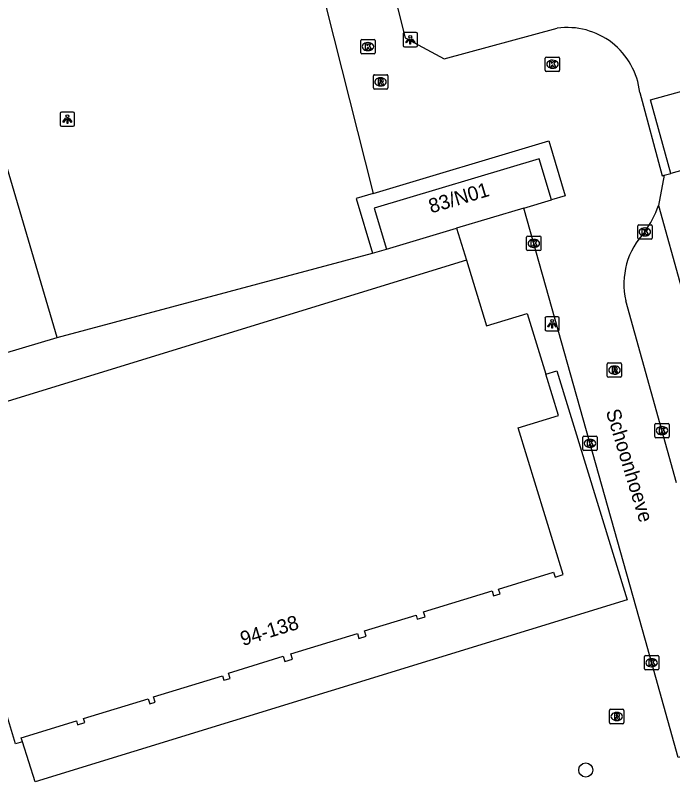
# Model space of a CAD drawing. Extents: x 161801 to 162379, y 382315 to 382832.
# Drawn here: x 161896.7 to 161942.5, y 382359.5 to 382412.7 of the extents above; entities that cross this region are included whole.
import ezdxf

# ---------------------------------------------------------------- set-up
doc = ezdxf.new("R2010")
doc.units = 0
for name, color, linetype in [('IMGEO_Boom', 7, 'Continuous'), ('IMGEO_Kolk', 7, 'Continuous'), ('IMGEO_Lichtpunt', 7, 'Continuous'), ('IMGEO_Openbare_ruimte_label', 7, 'Continuous'), ('IMGEO_Pand', 7, 'Continuous'), ('IMGEO_Pand_nummerreeks', 7, 'Continuous'), ('IMGEO_Rijbaan_lokaal_open', 7, 'Continuous'), ('IMGEO_Rioolput', 7, 'Continuous'), ('IMGEO_Voetpad_open', 7, 'Continuous')]:
    doc.layers.add(name, color=color, linetype=linetype)

msp = doc.modelspace()

# ---------------------------------------------------------------- linework, layer by layer
at = {"layer": 'IMGEO_Boom'}
msp.add_circle((161936.434, 382360.086), 0.489, dxfattribs=at)
at = {"layer": 'IMGEO_Kolk'}
for p, q in [((161920.83, 382411.017), (161921.682, 382411.017)), ((161920.755, 382410.091), (161920.755, 382410.943)), ((161921.243, 382410.797), (161921.268, 382410.797)), ((161921.756, 382410.943), (161921.756, 382410.091)), ((161921.682, 382410.017), (161920.83, 382410.017)), ((161921.266, 382410.237), (161921.241, 382410.237)), ((161933.616, 382408.865), (161933.616, 382409.717)), ((161933.691, 382409.791), (161934.543, 382409.791)), ((161934.104, 382409.571), (161934.129, 382409.571)), ((161934.617, 382409.717), (161934.617, 382408.865)), ((161934.127, 382409.011), (161934.102, 382409.011)), ((161934.543, 382408.791), (161933.691, 382408.791)), ((161940.056, 382397.172), (161940.056, 382398.024)), ((161940.131, 382398.098), (161940.983, 382398.098)), ((161940.544, 382397.878), (161940.569, 382397.878)), ((161941.057, 382398.024), (161941.057, 382397.172)), ((161932.316, 382396.372), (161932.316, 382397.224)), ((161932.391, 382397.298), (161933.243, 382397.298)), ((161933.317, 382397.224), (161933.317, 382396.372)), ((161940.567, 382397.318), (161940.542, 382397.318)), ((161932.804, 382397.078), (161932.829, 382397.078)), ((161940.983, 382397.098), (161940.131, 382397.098)), ((161933.243, 382396.298), (161932.391, 382396.298)), ((161932.827, 382396.518), (161932.802, 382396.518)), ((161941.247, 382383.326), (161941.247, 382384.178)), ((161941.322, 382384.252), (161942.174, 382384.252)), ((161941.735, 382384.032), (161941.76, 382384.032)), ((161942.248, 382384.178), (161942.248, 382383.326)), ((161936.306, 382383.359), (161937.158, 382383.359)), ((161941.758, 382383.472), (161941.733, 382383.472)), ((161936.231, 382382.433), (161936.231, 382383.285)), ((161936.719, 382383.139), (161936.744, 382383.139)), ((161937.232, 382383.285), (161937.232, 382382.433)), ((161942.174, 382383.252), (161941.322, 382383.252)), ((161937.158, 382382.359), (161936.306, 382382.359)), ((161936.742, 382382.579), (161936.717, 382382.579)), ((161940.526, 382367.136), (161940.526, 382367.988)), ((161940.601, 382368.062), (161941.453, 382368.062)), ((161941.527, 382367.988), (161941.527, 382367.136)), ((161941.014, 382367.842), (161941.039, 382367.842)), ((161941.453, 382367.062), (161940.601, 382367.062)), ((161941.037, 382367.282), (161941.012, 382367.282))]:
    msp.add_line(p, q, dxfattribs=at)
for points in [[(161920.83, 382411.017), (161921.682, 382411.017)], [(161920.755, 382410.091), (161920.755, 382410.943)], [(161921.076, 382410.717), (161921.199, 382410.717), (161921.199, 382410.566), (161921.329, 382410.717), (161921.493, 382410.717), (161921.347, 382410.566), (161921.5, 382410.317), (161921.348, 382410.317), (161921.263, 382410.481), (161921.199, 382410.414), (161921.199, 382410.317), (161921.076, 382410.317), (161921.076, 382410.717)], [(161921.756, 382410.943), (161921.756, 382410.091)], [(161921.682, 382410.017), (161920.83, 382410.017)], [(161933.616, 382408.865), (161933.616, 382409.717)], [(161933.691, 382409.791), (161934.543, 382409.791)], [(161933.937, 382409.491), (161934.06, 382409.491), (161934.06, 382409.34), (161934.19, 382409.491), (161934.354, 382409.491), (161934.208, 382409.34), (161934.361, 382409.091), (161934.209, 382409.091), (161934.124, 382409.255), (161934.06, 382409.188), (161934.06, 382409.091), (161933.937, 382409.091), (161933.937, 382409.491)], [(161934.617, 382409.717), (161934.617, 382408.865)], [(161934.543, 382408.791), (161933.691, 382408.791)], [(161940.056, 382397.172), (161940.056, 382398.024)], [(161940.131, 382398.098), (161940.983, 382398.098)], [(161940.377, 382397.798), (161940.5, 382397.798), (161940.5, 382397.647), (161940.63, 382397.798), (161940.794, 382397.798), (161940.648, 382397.647), (161940.801, 382397.398), (161940.649, 382397.398), (161940.564, 382397.562), (161940.5, 382397.495), (161940.5, 382397.398), (161940.377, 382397.398), (161940.377, 382397.798)], [(161941.057, 382398.024), (161941.057, 382397.172)], [(161932.316, 382396.372), (161932.316, 382397.224)], [(161932.391, 382397.298), (161933.243, 382397.298)], [(161933.317, 382397.224), (161933.317, 382396.372)], [(161932.637, 382396.998), (161932.76, 382396.998), (161932.76, 382396.847), (161932.89, 382396.998), (161933.054, 382396.998), (161932.908, 382396.847), (161933.061, 382396.598), (161932.909, 382396.598), (161932.824, 382396.762), (161932.76, 382396.695), (161932.76, 382396.598), (161932.637, 382396.598), (161932.637, 382396.998)], [(161940.983, 382397.098), (161940.131, 382397.098)], [(161933.243, 382396.298), (161932.391, 382396.298)], [(161941.247, 382383.326), (161941.247, 382384.178)], [(161941.322, 382384.252), (161942.174, 382384.252)], [(161941.568, 382383.952), (161941.691, 382383.952), (161941.691, 382383.801), (161941.821, 382383.952), (161941.985, 382383.952), (161941.839, 382383.801), (161941.992, 382383.552), (161941.84, 382383.552), (161941.755, 382383.716), (161941.691, 382383.649), (161941.691, 382383.552), (161941.568, 382383.552), (161941.568, 382383.952)], [(161942.248, 382384.178), (161942.248, 382383.326)], [(161936.306, 382383.359), (161937.158, 382383.359)], [(161936.231, 382382.433), (161936.231, 382383.285)], [(161936.552, 382383.059), (161936.675, 382383.059), (161936.675, 382382.908), (161936.805, 382383.059), (161936.969, 382383.059), (161936.823, 382382.908), (161936.976, 382382.659), (161936.824, 382382.659), (161936.739, 382382.823), (161936.675, 382382.756), (161936.675, 382382.659), (161936.552, 382382.659), (161936.552, 382383.059)], [(161937.232, 382383.285), (161937.232, 382382.433)], [(161942.174, 382383.252), (161941.322, 382383.252)], [(161937.158, 382382.359), (161936.306, 382382.359)], [(161940.526, 382367.136), (161940.526, 382367.988)], [(161940.601, 382368.062), (161941.453, 382368.062)], [(161941.527, 382367.988), (161941.527, 382367.136)], [(161940.847, 382367.762), (161940.97, 382367.762), (161940.97, 382367.611), (161941.1, 382367.762), (161941.264, 382367.762), (161941.118, 382367.611), (161941.271, 382367.362), (161941.119, 382367.362), (161941.034, 382367.526), (161940.97, 382367.459), (161940.97, 382367.362), (161940.847, 382367.362), (161940.847, 382367.762)], [(161941.453, 382367.062), (161940.601, 382367.062)]]:
    msp.add_lwpolyline(points, dxfattribs=at)
for centre, start, end in [((161920.832, 382410.941), 91.552, 178.448), ((161920.832, 382410.941), 91.552, 178.448), ((161921.68, 382410.941), 1.552, 88.448), ((161921.68, 382410.941), 1.552, 88.448), ((161920.832, 382410.093), 181.552, 268.448), ((161920.832, 382410.093), 181.552, 268.448), ((161921.68, 382410.093), 271.552, 358.448), ((161921.68, 382410.093), 271.552, 358.448), ((161933.693, 382409.715), 91.552, 178.448), ((161933.693, 382409.715), 91.552, 178.448), ((161934.541, 382409.715), 1.552, 88.448), ((161934.541, 382409.715), 1.552, 88.448), ((161933.693, 382408.867), 181.552, 268.448), ((161933.693, 382408.867), 181.552, 268.448), ((161934.541, 382408.867), 271.552, 358.448), ((161934.541, 382408.867), 271.552, 358.448), ((161940.133, 382398.022), 91.552, 178.448), ((161940.133, 382398.022), 91.552, 178.448), ((161940.981, 382398.022), 1.552, 88.448), ((161940.981, 382398.022), 1.552, 88.448), ((161932.393, 382397.222), 91.552, 178.448), ((161932.393, 382397.222), 91.552, 178.448), ((161933.241, 382397.222), 1.552, 88.448), ((161933.241, 382397.222), 1.552, 88.448), ((161940.133, 382397.174), 181.552, 268.448), ((161940.133, 382397.174), 181.552, 268.448), ((161940.981, 382397.174), 271.552, 358.448), ((161940.981, 382397.174), 271.552, 358.448), ((161932.393, 382396.374), 181.552, 268.448), ((161932.393, 382396.374), 181.552, 268.448), ((161933.241, 382396.374), 271.552, 358.448), ((161933.241, 382396.374), 271.552, 358.448), ((161941.324, 382384.176), 91.552, 178.448), ((161941.324, 382384.176), 91.552, 178.448), ((161942.172, 382384.176), 1.552, 88.448), ((161942.172, 382384.176), 1.552, 88.448), ((161936.308, 382383.283), 91.552, 178.448), ((161936.308, 382383.283), 91.552, 178.448), ((161937.156, 382383.283), 1.552, 88.448), ((161937.156, 382383.283), 1.552, 88.448), ((161941.324, 382383.328), 181.552, 268.448), ((161941.324, 382383.328), 181.552, 268.448), ((161942.172, 382383.328), 271.552, 358.448), ((161942.172, 382383.328), 271.552, 358.448), ((161936.308, 382382.435), 181.552, 268.448), ((161936.308, 382382.435), 181.552, 268.448), ((161937.156, 382382.435), 271.552, 358.448), ((161937.156, 382382.435), 271.552, 358.448), ((161940.603, 382367.986), 91.552, 178.448), ((161940.603, 382367.986), 91.552, 178.448), ((161941.451, 382367.986), 1.552, 88.448), ((161941.451, 382367.986), 1.552, 88.448), ((161940.603, 382367.138), 181.552, 268.448), ((161940.603, 382367.138), 181.552, 268.448), ((161941.451, 382367.138), 271.552, 358.448), ((161941.451, 382367.138), 271.552, 358.448)]:
    msp.add_arc(centre, 0.0765, start, end, dxfattribs=at)
for centre, major_axis, ratio, start_param, end_param in [((161921.242, 382410.517), (-0.387, 0.002), 0.722429, 4.712389, 7.853982), ((161921.267, 382410.517), (-0.39, 0.002), 0.717154, 1.570796, 4.712389), ((161934.103, 382409.291), (-0.387, 0.002), 0.722429, 4.712389, 7.853982), ((161934.128, 382409.291), (-0.39, 0.002), 0.717154, 1.570796, 4.712389), ((161940.543, 382397.598), (-0.387, 0.002), 0.722429, 4.712389, 7.853982), ((161940.568, 382397.598), (-0.39, 0.002), 0.717154, 1.570796, 4.712389), ((161932.803, 382396.798), (-0.387, 0.002), 0.722429, 4.712389, 7.853982), ((161932.828, 382396.798), (-0.39, 0.002), 0.717154, 1.570796, 4.712389), ((161941.734, 382383.752), (-0.387, 0.002), 0.722429, 4.712389, 7.853982), ((161941.759, 382383.752), (-0.39, 0.002), 0.717154, 1.570796, 4.712389), ((161936.718, 382382.859), (-0.387, 0.002), 0.722429, 4.712389, 7.853982), ((161936.743, 382382.859), (-0.39, 0.002), 0.717154, 1.570796, 4.712389), ((161941.013, 382367.562), (-0.387, 0.002), 0.722429, 4.712389, 7.853982), ((161941.038, 382367.562), (-0.39, 0.002), 0.717154, 1.570796, 4.712389)]:
    msp.add_ellipse(centre, major_axis=major_axis, ratio=ratio, start_param=start_param, end_param=end_param, dxfattribs=at)
at = {"layer": 'IMGEO_Lichtpunt'}
for p, q in [((161923.708, 382411.404), (161923.708, 382410.597)), ((161923.708, 382411.404), (161923.708, 382410.597)), ((161924.61, 382411.499), (161923.802, 382411.499)), ((161924.61, 382411.499), (161923.802, 382411.499)), ((161924.704, 382410.597), (161924.704, 382411.404)), ((161924.704, 382410.597), (161924.704, 382411.404)), ((161923.802, 382410.503), (161924.61, 382410.503)), ((161923.802, 382410.503), (161924.61, 382410.503)), ((161899.815, 382405.862), (161899.815, 382405.055)), ((161899.815, 382405.862), (161899.815, 382405.055)), ((161900.717, 382405.957), (161899.909, 382405.957)), ((161900.717, 382405.957), (161899.909, 382405.957)), ((161900.811, 382405.055), (161900.811, 382405.862)), ((161900.811, 382405.055), (161900.811, 382405.862)), ((161899.909, 382404.961), (161900.717, 382404.961)), ((161899.909, 382404.961), (161900.717, 382404.961)), ((161933.596, 382391.594), (161933.596, 382390.787)), ((161933.596, 382391.594), (161933.596, 382390.787)), ((161934.498, 382391.689), (161933.69, 382391.689)), ((161934.498, 382391.689), (161933.69, 382391.689)), ((161934.592, 382390.787), (161934.592, 382391.594)), ((161934.592, 382390.787), (161934.592, 382391.594)), ((161933.69, 382390.693), (161934.498, 382390.693)), ((161933.69, 382390.693), (161934.498, 382390.693))]:
    msp.add_line(p, q, dxfattribs=at)
for points in [[(161924.082, 382411.068), (161924.121, 382411.04), (161923.933, 382410.778), (161923.895, 382410.805), (161924.082, 382411.068)], [(161924.184, 382411.02), (161924.231, 382411.02), (161924.231, 382410.698), (161924.184, 382410.698), (161924.184, 382411.02)], [(161924.294, 382411.04), (161924.332, 382411.067), (161924.519, 382410.805), (161924.48, 382410.777), (161924.294, 382411.04)], [(161900.189, 382405.526), (161900.228, 382405.498), (161900.04, 382405.236), (161900.002, 382405.263), (161900.189, 382405.526)], [(161900.291, 382405.478), (161900.338, 382405.478), (161900.338, 382405.156), (161900.291, 382405.156), (161900.291, 382405.478)], [(161900.401, 382405.498), (161900.439, 382405.525), (161900.626, 382405.263), (161900.587, 382405.235), (161900.401, 382405.498)], [(161933.97, 382391.258), (161934.009, 382391.23), (161933.821, 382390.968), (161933.783, 382390.995), (161933.97, 382391.258)], [(161934.072, 382391.21), (161934.119, 382391.21), (161934.119, 382390.888), (161934.072, 382390.888), (161934.072, 382391.21)], [(161934.182, 382391.23), (161934.22, 382391.257), (161934.407, 382390.995), (161934.368, 382390.967), (161934.182, 382391.23)]]:
    msp.add_lwpolyline(points, dxfattribs=at)
for centre in [(161924.207, 382411.202), (161900.314, 382405.66), (161934.095, 382391.392)]:
    msp.add_circle(centre, 0.0994, dxfattribs=at)
for centre, start, end in [((161923.802, 382411.404), 90, 180), ((161923.802, 382411.404), 90, 180), ((161924.61, 382411.404), 0, 90), ((161924.61, 382411.404), 0, 90), ((161923.802, 382410.597), 180, 270), ((161923.802, 382410.597), 180, 270), ((161924.61, 382410.597), 270, 0), ((161924.61, 382410.597), 270, 360), ((161899.909, 382405.862), 90, 180), ((161899.909, 382405.862), 90, 180), ((161900.717, 382405.862), 0, 90), ((161900.717, 382405.862), 0, 90), ((161899.909, 382405.055), 180, 270), ((161899.909, 382405.055), 180, 270), ((161900.717, 382405.055), 270, 0), ((161900.717, 382405.055), 270, 360), ((161933.69, 382391.594), 90, 180), ((161933.69, 382391.594), 90, 180), ((161934.498, 382391.594), 0, 90), ((161934.498, 382391.594), 0, 90), ((161933.69, 382390.787), 180, 270), ((161933.69, 382390.787), 180, 270), ((161934.498, 382390.787), 270, 0), ((161934.498, 382390.787), 270, 360)]:
    msp.add_arc(centre, 0.0946, start, end, dxfattribs=at)
at = {"layer": 'IMGEO_Pand'}
for points in [[(161942.37, 382401.676), (161940.944, 382406.8), (161949.609, 382409.212), (161951.302, 382407.048)], [(161951.302, 382407.048), (161952.02, 382404.363), (161942.37, 382401.676)], [(161899.598, 382390.231), (161895.348, 382404.595)], [(161941.516, 382399.444), (161943.116, 382393.678), (161980.926, 382404.082)], [(161934.047, 382399.831), (161933.186, 382402.705), (161921.692, 382399.261), (161922.553, 382396.388)], [(161941.909, 382401.548), (161941.516, 382399.444)], [(161941.909, 382401.548), (161942.37, 382401.676)], [(161932.127, 382399.256), (161934.047, 382399.831)], [(161932.127, 382399.256), (161927.439, 382397.852)], [(161922.553, 382396.388), (161927.439, 382397.852)], [(161928.121, 382395.631), (161889.82, 382383.852)], [(161928.121, 382395.631), (161929.53, 382391.05), (161932.357, 382391.919), (161933.661, 382387.68)], [(161888.821, 382387.042), (161899.598, 382390.231)], [(161897.188, 382362.052), (161897.101, 382362.335), (161900.941, 382363.516), (161901.025, 382363.242), (161901.529, 382363.397), (161901.444, 382363.675), (161905.943, 382365.058), (161906.052, 382364.703), (161906.437, 382364.821), (161906.326, 382365.183), (161911.129, 382366.66), (161911.227, 382366.341), (161911.647, 382366.47), (161911.533, 382366.842), (161915.346, 382368.014), (161915.461, 382367.641), (161915.999, 382367.807), (161915.884, 382368.182), (161920.524, 382369.609), (161920.63, 382369.265), (161921.136, 382369.42), (161921.025, 382369.779), (161924.607, 382370.881), (161924.696, 382370.591), (161925.238, 382370.757), (161925.131, 382371.103), (161929.908, 382372.572), (161930.014, 382372.228), (161930.466, 382372.367), (161930.367, 382372.691), (161934.198, 382373.869), (161934.3, 382373.54), (161934.872, 382373.716), (161931.73, 382383.935), (161934.546, 382384.801), (161933.661, 382387.68)], [(161897.188, 382362.052), (161896.699, 382361.902), (161895.555, 382365.624)]]:
    msp.add_lwpolyline(points, dxfattribs=at)
at = {"layer": 'IMGEO_Rijbaan_lokaal_open'}
for points in [[(161910.817, 382462.697), (161923.855, 382411.141), (161926.575, 382409.655), (161934.439, 382411.796)], [(161906.292, 382461), (161921.617, 382400.283)], [(161940.197, 382407.325), (161941.76, 382401.512), (161941.909, 382401.548)], [(161921.617, 382400.283), (161933.857, 382403.95), (161935.005, 382400.118), (161934.047, 382399.831)], [(161947.708, 382362.337), (161942.874, 382360.967), (161940.588, 382369.122), (161932.127, 382399.256)], [(161942.76, 382380.116), (161939.23, 382392.79)]]:
    msp.add_lwpolyline(points, dxfattribs=at)
for centre, radius, start, end in [((161935.153, 382406.772), 5.074, 6.2564, 98.086), ((161932.118, 382403.154), 10.104, 326.6397, 338.4564), ((161944.322, 382393.972), 5.228, 136.078, 193.0632)]:
    msp.add_arc(centre, radius, start, end, dxfattribs=at)
at = {"layer": 'IMGEO_Rioolput'}
for p, q in [((161921.637, 382407.635), (161921.637, 382408.487)), ((161921.712, 382408.561), (161922.564, 382408.561)), ((161922.125, 382408.341), (161922.15, 382408.341)), ((161922.638, 382408.487), (161922.638, 382407.635)), ((161922.564, 382407.561), (161921.712, 382407.561)), ((161922.148, 382407.781), (161922.123, 382407.781)), ((161937.935, 382387.538), (161937.935, 382388.39)), ((161938.01, 382388.464), (161938.862, 382388.464)), ((161938.423, 382388.244), (161938.448, 382388.244)), ((161938.936, 382388.39), (161938.936, 382387.538)), ((161938.446, 382387.684), (161938.421, 382387.684)), ((161938.862, 382387.464), (161938.01, 382387.464)), ((161938.095, 382363.391), (161938.095, 382364.243)), ((161938.17, 382364.317), (161939.022, 382364.317)), ((161939.096, 382364.243), (161939.096, 382363.391)), ((161938.583, 382364.097), (161938.608, 382364.097)), ((161939.022, 382363.317), (161938.17, 382363.317)), ((161938.606, 382363.537), (161938.581, 382363.537))]:
    msp.add_line(p, q, dxfattribs=at)
for points in [[(161921.637, 382407.635), (161921.637, 382408.487)], [(161921.712, 382408.561), (161922.564, 382408.561)], [(161922.638, 382408.487), (161922.638, 382407.635)], [(161922.226, 382408.259), (161921.974, 382408.261), (161921.974, 382407.861)], [(161921.974, 382407.861), (161922.098, 382407.861), (161922.098, 382408.023), (161922.109, 382408.023)], [(161922.152, 382408.18), (161922.098, 382408.18), (161922.098, 382408.099)], [(161922.098, 382408.099), (161922.15, 382408.099)], [(161922.156, 382407.994), (161922.227, 382407.861), (161922.367, 382407.861), (161922.302, 382407.987)], [(161922.564, 382407.561), (161921.712, 382407.561)], [(161937.935, 382387.538), (161937.935, 382388.39)], [(161938.01, 382388.464), (161938.862, 382388.464)], [(161938.524, 382388.162), (161938.272, 382388.164), (161938.272, 382387.764)], [(161938.936, 382388.39), (161938.936, 382387.538)], [(161938.272, 382387.764), (161938.396, 382387.764), (161938.396, 382387.926), (161938.407, 382387.926)], [(161938.45, 382388.083), (161938.396, 382388.083), (161938.396, 382388.002)], [(161938.396, 382388.002), (161938.448, 382388.002)], [(161938.454, 382387.897), (161938.525, 382387.764), (161938.665, 382387.764), (161938.6, 382387.89)], [(161938.862, 382387.464), (161938.01, 382387.464)], [(161938.095, 382363.391), (161938.095, 382364.243)], [(161938.17, 382364.317), (161939.022, 382364.317)], [(161939.096, 382364.243), (161939.096, 382363.391)], [(161938.684, 382364.015), (161938.432, 382364.017), (161938.432, 382363.617)], [(161938.432, 382363.617), (161938.556, 382363.617), (161938.556, 382363.779), (161938.567, 382363.779)], [(161938.61, 382363.936), (161938.556, 382363.936), (161938.556, 382363.855)], [(161938.556, 382363.855), (161938.608, 382363.855)], [(161938.614, 382363.75), (161938.685, 382363.617), (161938.825, 382363.617), (161938.76, 382363.743)], [(161939.022, 382363.317), (161938.17, 382363.317)]]:
    msp.add_lwpolyline(points, dxfattribs=at)
for centre, radius, start, end in [((161921.714, 382408.485), 0.0765, 91.552, 178.448), ((161921.714, 382408.485), 0.0765, 91.552, 178.448), ((161922.562, 382408.485), 0.0765, 1.552, 88.448), ((161922.562, 382408.485), 0.0765, 1.552, 88.448), ((161922.108, 382407.97), 0.0533, 26.0293, 88.6989), ((161922.134, 382408.288), 0.19, 274.7715, 282.9687), ((161922.158, 382408.084), 0.0964, 77.0061, 93.1865), ((161922.172, 382408.141), 0.0378, 276.6634, 79.6772), ((161922.225, 382408.149), 0.109, 350.3612, 89.416), ((161922.223, 382408.149), 0.112, 277.5842, 350.9817), ((161922.207, 382407.934), 0.108, 29.5134, 73.7905), ((161921.714, 382407.637), 0.0765, 181.552, 268.448), ((161921.714, 382407.637), 0.0765, 181.552, 268.448), ((161922.562, 382407.637), 0.0765, 271.552, 358.448), ((161922.562, 382407.637), 0.0765, 271.552, 358.448), ((161938.012, 382388.388), 0.0765, 91.552, 178.448), ((161938.012, 382388.388), 0.0765, 91.552, 178.448), ((161938.523, 382388.052), 0.109, 350.3612, 89.416), ((161938.86, 382388.388), 0.0765, 1.552, 88.448), ((161938.86, 382388.388), 0.0765, 1.552, 88.448), ((161938.406, 382387.873), 0.0533, 26.0293, 88.6989), ((161938.432, 382388.191), 0.19, 274.7715, 282.9687), ((161938.456, 382387.987), 0.0964, 77.0061, 93.1865), ((161938.47, 382388.044), 0.0378, 276.6634, 79.6772), ((161938.521, 382388.052), 0.112, 277.5842, 350.9817), ((161938.505, 382387.837), 0.108, 29.5134, 73.7905), ((161938.012, 382387.54), 0.0765, 181.552, 268.448), ((161938.012, 382387.54), 0.0765, 181.552, 268.448), ((161938.86, 382387.54), 0.0765, 271.552, 358.448), ((161938.86, 382387.54), 0.0765, 271.552, 358.448), ((161938.172, 382364.241), 0.0765, 91.552, 178.448), ((161938.172, 382364.241), 0.0765, 91.552, 178.448), ((161939.02, 382364.241), 0.0765, 1.552, 88.448), ((161939.02, 382364.241), 0.0765, 1.552, 88.448), ((161938.566, 382363.726), 0.0533, 26.0293, 88.6989), ((161938.592, 382364.044), 0.19, 274.7715, 282.9687), ((161938.616, 382363.84), 0.0964, 77.0061, 93.1865), ((161938.63, 382363.897), 0.0378, 276.6634, 79.6772), ((161938.683, 382363.905), 0.109, 350.3612, 89.416), ((161938.681, 382363.905), 0.112, 277.5842, 350.9817), ((161938.665, 382363.69), 0.108, 29.5134, 73.7905), ((161938.172, 382363.393), 0.0765, 181.552, 268.448), ((161938.172, 382363.393), 0.0765, 181.552, 268.448), ((161939.02, 382363.393), 0.0765, 271.552, 358.448), ((161939.02, 382363.393), 0.0765, 271.552, 358.448)]:
    msp.add_arc(centre, radius, start, end, dxfattribs=at)
for centre, major_axis, ratio, start_param, end_param in [((161922.124, 382408.061), (-0.387, 0.002), 0.722429, 4.712389, 7.853982), ((161922.149, 382408.061), (-0.39, 0.002), 0.717154, 1.570796, 4.712389), ((161938.422, 382387.964), (-0.387, 0.002), 0.722429, 4.712389, 7.853982), ((161938.447, 382387.964), (-0.39, 0.002), 0.717154, 1.570796, 4.712389), ((161938.582, 382363.817), (-0.387, 0.002), 0.722429, 4.712389, 7.853982), ((161938.607, 382363.817), (-0.39, 0.002), 0.717154, 1.570796, 4.712389)]:
    msp.add_ellipse(centre, major_axis=major_axis, ratio=ratio, start_param=start_param, end_param=end_param, dxfattribs=at)
at = {"layer": 'IMGEO_Voetpad_open'}
for points in [[(161921.617, 382400.283), (161920.447, 382399.932), (161921.586, 382396.128)], [(161927.439, 382397.852), (161928.121, 382395.631)], [(161899.598, 382390.231), (161921.586, 382396.128)], [(161921.586, 382396.128), (161922.553, 382396.388)], [(161933.661, 382387.68), (161934.42, 382387.913), (161939.328, 382371.953), (161898.08, 382359.268)], [(161898.08, 382359.268), (161897.188, 382362.052)]]:
    msp.add_lwpolyline(points, dxfattribs=at)

# ---------------------------------------------------------------- texts
at = {"layer": 'IMGEO_Openbare_ruimte_label'}
msp.add_text('Schoonhoeve', height=1, rotation=286.9132, dxfattribs=at).set_placement((161937.824, 382385.088))
at = {"layer": 'IMGEO_Pand_nummerreeks'}
for s, rotation, p in [('83/N01', 16.6723, (161925.663, 382398.886)), ('94-138', 17.0949, (161912.542, 382368.724))]:
    msp.add_text(s, height=1, rotation=rotation, dxfattribs=at).set_placement(p)

doc.saveas('drawing.dxf')
